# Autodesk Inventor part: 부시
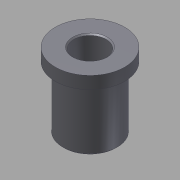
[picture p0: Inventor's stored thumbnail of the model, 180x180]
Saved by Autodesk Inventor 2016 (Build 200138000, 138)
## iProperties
Company: 한국ATC센터
Created: 2015-11
Part Number: 부시
Document SubType Name: Modeling
Designer: mdu
Density: 7.86 g/cm^3
Material: 강철, 연강
Mass: 67.4477 g
Surface Area: 43.1512 cm^2
Volume: 8.58113 cm^3
Appearance: 강철
Author: mdu
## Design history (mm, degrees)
sketch "스케치1"
  geometry: C1 r 11 at (0, 0) reference; C2 r 14 at (0, 0) reference; C3 r 11 at (0, 0) reference; 1 further point
  node "참조1"
  node "참조2"
extrude "돌출1" new body sketch "스케치1" distance "d0" = 5; taper "d1" = 0 deg
extrude "돌출2" join sketch "스케치1" distance "d2" = 25; taper "d3" = 0 deg
hole "구멍1" diameter "d6" = 13; stored, may be unused: countersink angle "d10" = 90 deg, drill point angle "d12" = 118 deg; dims "d4" = 10, "d5" = 10, "d7" = 6, "d8" = 4, "d9" = 2, "d11" = 8
chamfer "모따기1" distance "d13" = 0.5; stored, may be unused: second distance "d14" = 2, angle "d15" = 45 deg
chamfer "모따기2" distance "d16" = 0.5; stored, may be unused: second distance "d17" = 2, angle "d18" = 45 deg
node "솔리드1"
